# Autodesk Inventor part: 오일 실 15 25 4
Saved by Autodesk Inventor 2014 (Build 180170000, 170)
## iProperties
Created: 2025-06
Part Number: 오일 실 15 25 4
Material: 일반
Document SubType Name: Modeling
Designer: dg
Density: 1 g/cm^3
Appearance: 기본값
Author: dg
Author: jhkim
Description: 오일 실 - 비스프링, 조립 GA
Creation Date: 2025-05-27
Sending System: Autodesk Inventor 2026
Preprocessor: ST-DEVELOPER v20.1
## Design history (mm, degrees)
node "오일 실 15 25 41"
body "Solid1"
node "기준1"
